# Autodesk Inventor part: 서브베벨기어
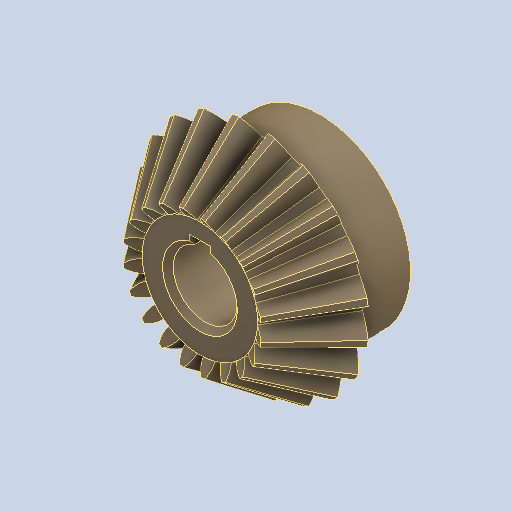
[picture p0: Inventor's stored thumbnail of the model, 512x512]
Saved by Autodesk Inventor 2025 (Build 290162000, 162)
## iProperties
Created: 2024-08
Part Number: 서브베벨기어
Material: 강철, 탄소
Document SubType Name: Modeling
Designer: rese9
Density: 7.87 g/cm^3
Appearance: 기본값
Author: jhkim
Sending System: Autodesk Inventor 2025
Preprocessor: ST-DEVELOPER v20
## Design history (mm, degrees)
node "복구된 형상1"
  node "스케치11"
feature "Solid1"
node "스케치10"
node "솔리드1"
